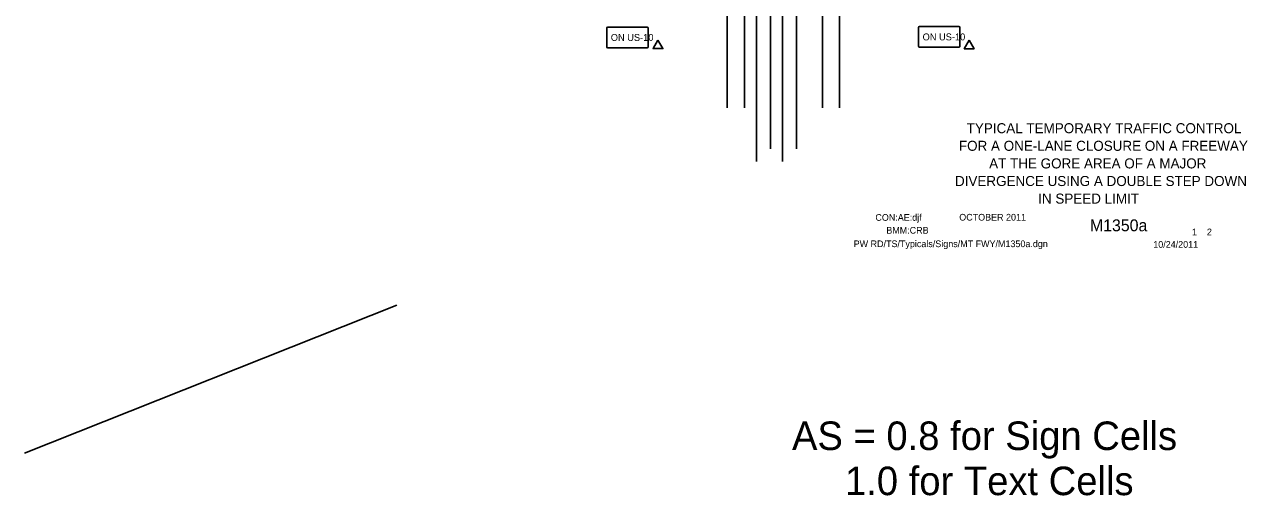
# Model space of a CAD drawing. Extents: x 16303 to 18479, y 5704 to 6974.
# Drawn here: x 16303 to 17435, y 5704 to 6140 of the extents above; entities that cross this region are included whole.
import ezdxf

# ---------------------------------------------------------------- set-up
doc = ezdxf.new("R2010")
doc.units = 0
for name, color, linetype in [('ALI_LEGAL_EX', 7, 'Continuous'), ('BORDER', 7, 'Continuous'), ('BORDER_SIGNAL_WO', 7, 'Continuous'), ('PAVT_EDGE_EX', 7, 'Continuous'), ('TRAFFIC_SIGNS_PR', 7, 'Continuous'), ('TYPICAL_TEXT_DIMEN_PR', 7, 'Continuous')]:
    doc.layers.add(name, color=color, linetype=linetype)

msp = doc.modelspace()

# ---------------------------------------------------------------- linework, layer by layer
at = {"layer": 'ALI_LEGAL_EX'}
for p, q in [((16980.7, 6877), (16980.7, 6013.1)), ((17004.7, 6877), (17004.7, 6013.1)), ((16993.6, 6024.8), (16993.6, 6525.1)), ((17017.6, 6024.8), (17017.6, 6525.1))]:
    msp.add_line(p, q, dxfattribs=at)
for points in [[(16993.6, 6124.8), (16993.6, 6149.8)], [(17017.6, 6124.8), (17017.6, 6149.8)], [(16993.6, 6049.8), (16993.6, 6024.8)]]:
    msp.add_lwpolyline(points, dxfattribs=at)
at = {"layer": 'PAVT_EDGE_EX'}
for p, q in [((16953.6, 6525.1), (16953.6, 6062.7)), ((16969.6, 6525.1), (16969.6, 6062.7)), ((17041.6, 6525.1), (17041.6, 6062.7)), ((17057.6, 6525.1), (17057.6, 6062.7))]:
    msp.add_line(p, q, dxfattribs=at)
at = {"layer": 'TRAFFIC_SIGNS_PR'}
for p, q in [((16842, 6136.5), (16842, 6119.3)), ((16843, 6137.5), (16879.4, 6137.5)), ((16880.4, 6136.5), (16880.4, 6119.3)), ((17130.5, 6137), (17130.5, 6119.8)), ((17131.5, 6138), (17168, 6138)), ((17169, 6137), (17169, 6119.8)), ((16843, 6118.3), (16879.4, 6118.3)), ((17131.5, 6118.8), (17168, 6118.8))]:
    msp.add_line(p, q, dxfattribs=at)
for centre, start, end in [((16843, 6136.5), 90, 180), ((16879.4, 6136.5), 0, 90), ((17131.5, 6137), 90, 180), ((17168, 6137), 0, 90), ((16843, 6119.3), 180, 270), ((16879.4, 6119.3), 270, 0), ((17131.5, 6119.8), 180, 270), ((17168, 6119.8), 270, 0)]:
    msp.add_arc(centre, 1, start, end, dxfattribs=at)
at = {"layer": 'TYPICAL_TEXT_DIMEN_PR'}
msp.add_line((16647.8, 5880), (16303.1, 5742.8), dxfattribs=at)
for points in [[(16889.4, 6125.5), (16884.9, 6117.6), (16894, 6117.6)], [(17177.5, 6125.3), (17173, 6117.4), (17182.1, 6117.4)]]:
    msp.add_lwpolyline(points, close=True, dxfattribs=at)

# ---------------------------------------------------------------- texts
at = {"layer": 'BORDER'}
for s, p in [('TYPICAL TEMPORARY TRAFFIC CONTROL', (17175.2, 6039.2)), ('FOR A ONE-LANE CLOSURE ON A FREEWAY', (17168, 6022.9)), ('AT THE GORE AREA OF A MAJOR', (17196, 6006.6)), ('DIVERGENCE USING A DOUBLE STEP DOWN ', (17164.4, 5990.3)), ('IN SPEED LIMIT', (17241.4, 5974))]:
    msp.add_text(s, height=9.3, dxfattribs=at).set_placement(p)
at = {"layer": 'BORDER_SIGNAL_WO'}
for s, height, p in [('CON:AE:djf  ', 6.2, (17090.7, 5958.1)), ('    OCTOBER 2011    ', 6.2, (17159.1, 5958.3)), ('    M1350a   ', 11, (17272.9, 5948.4)), ('BMM:CRB   ', 6.2, (17100.8, 5946.2)), (' 1    2 ', 6.2, (17381.4, 5944.7)), ('PW RD/TS/Typicals/Signs/MT FWY/M1350a.dgn      ', 6.2, (17070.6, 5933.7)), ('10/24/2011    ', 6.2, (17347.9, 5933.1)), ('AS = 0.8 for Sign Cells', 26.424, (17013.5, 5745.8)), ('     1.0 for Text Cells', 26.424, (17013.5, 5704))]:
    msp.add_text(s, height=height, dxfattribs=at).set_placement(p)
at = {"layer": 'TRAFFIC_SIGNS_PR'}
for p in [(16845.8, 6124.7), (17134.4, 6125.2)]:
    msp.add_text('ON US-10', height=6.4, dxfattribs=at).set_placement(p)

doc.saveas('drawing.dxf')
